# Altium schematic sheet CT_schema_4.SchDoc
size 283 x 147 mm
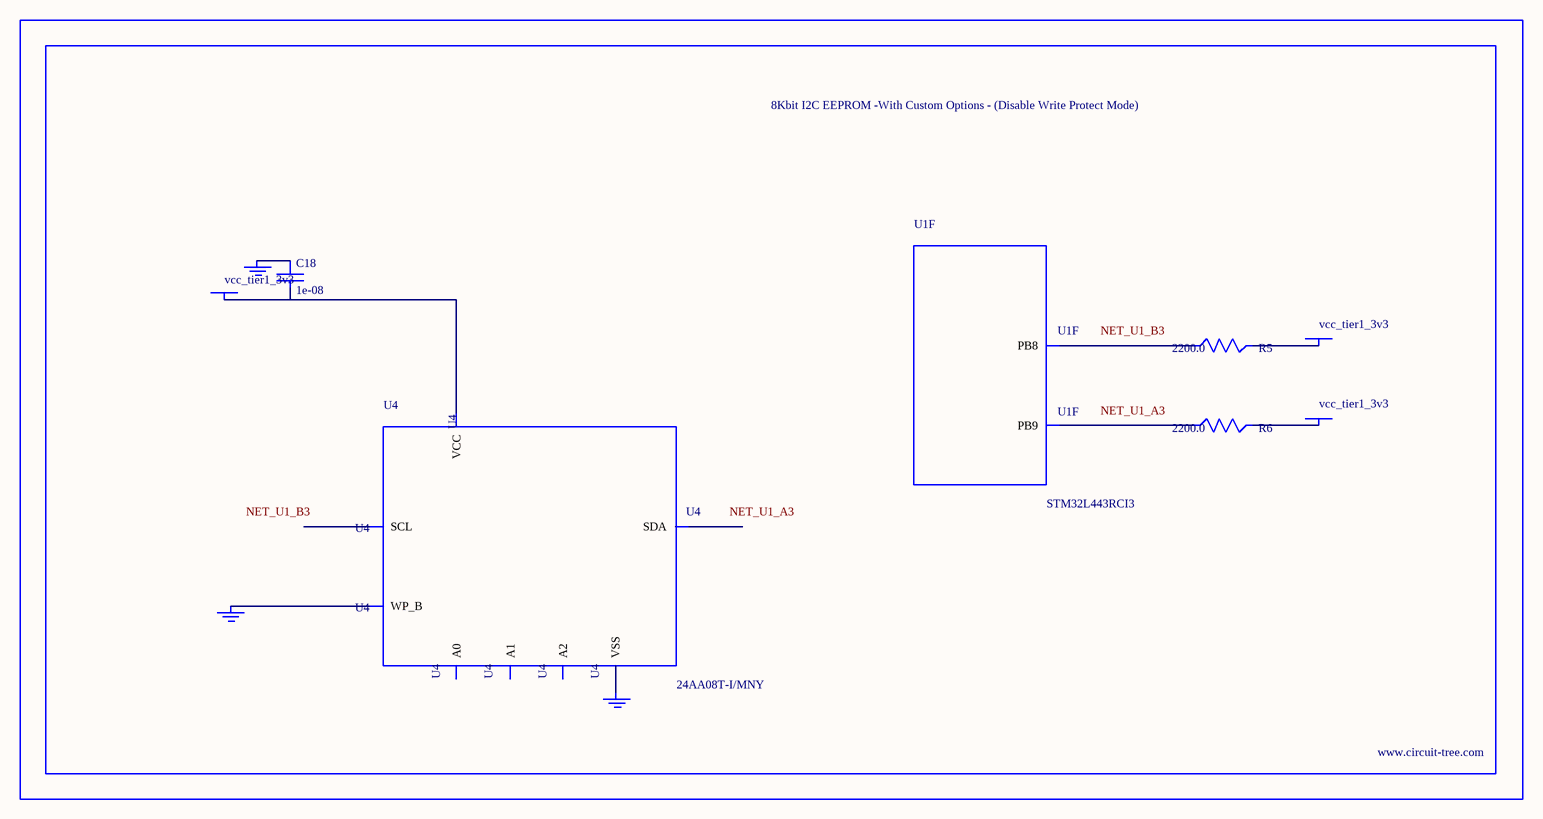
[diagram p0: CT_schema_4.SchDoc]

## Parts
BORDER3  (no value)
C18  1e-08  [C0402]
GND_INSTANCE_3_0  (no value)
GND_INSTANCE_3_1  (no value)
GND_INSTANCE_3_2  (no value)
POWER_INSTANCE_3_0  vcc_tier1_3v3
POWER_INSTANCE_3_1  vcc_tier1_3v3
POWER_INSTANCE_3_2  vcc_tier1_3v3
R5  2200.0  [R0603]
R6  2200.0  [R0603]
U1  STM32L443RCI3  [UFBGA64]  (part F of 8)
U4  24AA08T-I/MNY  [TDFN-8/6MM]

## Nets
NetC18_1: C18.1 GND_INSTANCE_3_1.0(GND)
NetC18_2: C18.2 POWER_INSTANCE_3_0.0(PWR) U4.8(VCC)
NetGND_INSTANCE_3_0_0: GND_INSTANCE_3_0.0(GND) U4.7(WP_B)
NetGND_INSTANCE_3_2_0: GND_INSTANCE_3_2.0(GND) U4.4(VSS)
NetPOWER_INSTANCE_3_1_0: POWER_INSTANCE_3_1.0(PWR) R5.2
NetPOWER_INSTANCE_3_2_0: POWER_INSTANCE_3_2.0(PWR) R6.2
NetR5_1: R5.1 U1.B3(PB8)
NetR6_1: R6.1 U1.A3(PB9)

Not connected (* = marked no-connect by the designer): U4 1(A0) 2(A1) 3(A2) 5(SDA) 6(SCL)

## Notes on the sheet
- Labels drawn without touching a wire or pin: NET_U1_A3, NET_U1_B3

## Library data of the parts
BORDER3 = BORDER_PAGE3
C18 = C0402C103K3RAC
GND_INSTANCE_3_0-GND_INSTANCE_3_2 = GND
POWER_INSTANCE_3_0-POWER_INSTANCE_3_2 = PWR
R5 R6 = RC0603JR-072K2L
